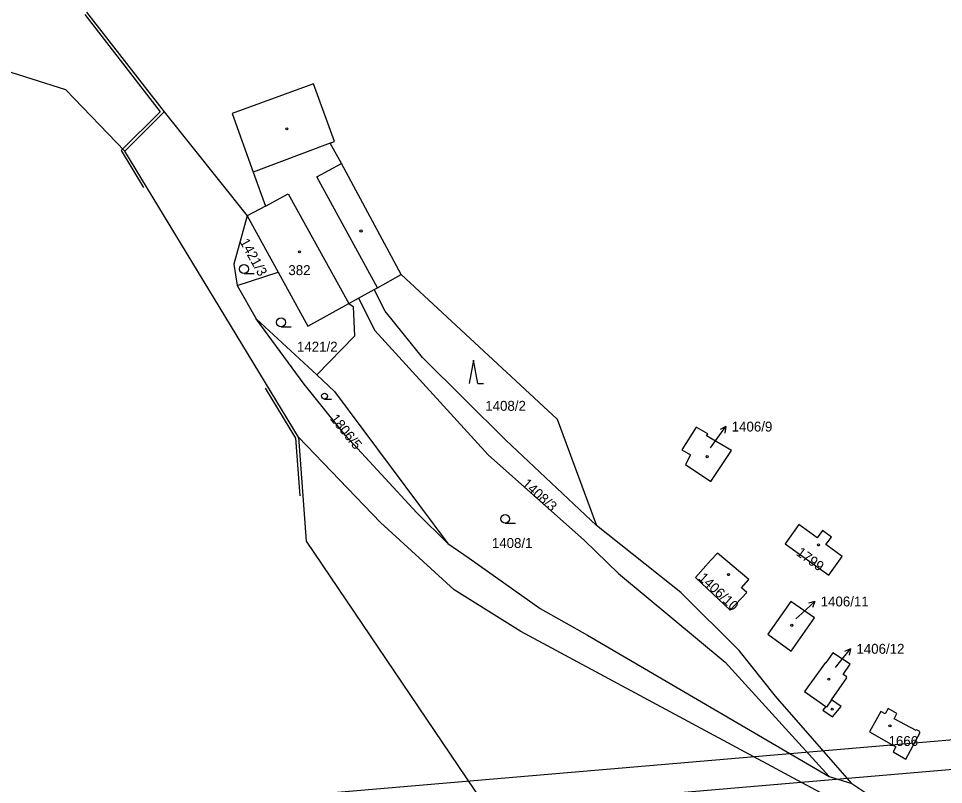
# Model space of a CAD drawing. Extents: x -779330 to -774454, y -1144748 to -1142831.
# Drawn here: x -778476.8 to -778318.4, y -1143557.2 to -1143426 of the extents above; entities that cross this region are included whole.
import ezdxf

# ---------------------------------------------------------------- set-up
doc = ezdxf.new("R2010")
doc.units = 0
for name, color, linetype in [('Hranice parcel', 7, 'Continuous'), ('Parcelní čísla', 7, 'Continuous'), ('Pop  PČ popisy', 7, 'Continuous'), ('Vnitřní kresba', 7, 'Continuous'), ('Vrstva 1', 7, 'Continuous'), ('Značky budov', 7, 'Continuous'), ('Značky kultur', 7, 'Continuous')]:
    doc.layers.add(name, color=color, linetype=linetype)

msp = doc.modelspace()

# ---------------------------------------------------------------- linework, layer by layer
at = {"layer": 'Hranice parcel'}
for p, q in [((-778465.13, -1143424.95), (-778451.86, -1143442.04)), ((-778468.65, -1143438.25), (-778504.96, -1143426.73)), ((-778458.56, -1143448.73), (-778468.65, -1143438.25)), ((-778458.56, -1143448.73), (-778451.86, -1143442.04)), ((-778451.86, -1143442.04), (-778437.65, -1143459.82)), ((-778428.85, -1143497.7), (-778458.56, -1143448.73)), ((-778437.65, -1143459.82), (-778432.35, -1143469.46)), ((-778439.35, -1143471.76), (-778432.35, -1143469.46)), ((-778439.35, -1143471.76), (-778436.1, -1143477.46)), ((-778418.6, -1143473.93), (-778415.92, -1143472.44)), ((-778420.24, -1143474.84), (-778418.6, -1143473.93)), ((-778436.1, -1143477.46), (-778425.71, -1143487.05)), ((-778427.89, -1143488.63), (-778436.1, -1143477.46)), ((-778419.29, -1143480.44), (-778425.71, -1143487.05)), ((-778403.28, -1143515.89), (-778408.6, -1143510.68)), ((-778403.28, -1143515.89), (-778399.61, -1143518.42)), ((-778338.03, -1143555.79), (-778334.13, -1143557.01))]:
    msp.add_line(p, q, dxfattribs=at)
for points in [[(-778411.25, -1143469.85), (-778421.51, -1143450.89), (-778423.42, -1143447.36), (-778422.68, -1143447.08), (-778426.28, -1143437.21), (-778440.22, -1143442.3), (-778436.59, -1143452.33), (-778434.47, -1143458.19), (-778437.65, -1143459.82)], [(-778437.65, -1143459.82), (-778439.93, -1143468.1), (-778439.35, -1143471.76)], [(-778432.35, -1143469.46), (-778427.25, -1143478.73), (-778420.24, -1143474.84)], [(-778415.92, -1143472.44), (-778415.35, -1143472.13), (-778411.25, -1143469.85)], [(-778411.25, -1143469.85), (-778384.6, -1143494.61), (-778377.84, -1143512.85)], [(-778377.84, -1143512.85), (-778393.35, -1143498.23), (-778407.6, -1143484.07), (-778414.02, -1143476.15), (-778415.92, -1143472.44)], [(-778420.24, -1143474.84), (-778419.49, -1143475.35), (-778419.29, -1143480.44)], [(-778418.6, -1143473.93), (-778415.77, -1143479.46), (-778396.37, -1143500.75), (-778379.92, -1143515.38), (-778374.08, -1143521.03), (-778355.81, -1143536.2), (-778338.03, -1143555.79)], [(-778425.71, -1143487.05), (-778422.69, -1143489.91), (-778403.28, -1143515.89)], [(-778408.6, -1143510.68), (-778420.83, -1143497.44), (-778427.89, -1143488.63)], [(-778363.25, -1143499.87), (-778361.75, -1143500.75), (-778362.6, -1143502.4), (-778358.29, -1143505.3), (-778354.71, -1143499.97), (-778358.99, -1143497.46), (-778358.81, -1143497.14), (-778360.79, -1143495.98), (-778363.25, -1143499.87)], [(-778273.31, -1143597.02), (-778277.63, -1143592.38), (-778304.71, -1143577.98), (-778330.53, -1143563.4), (-778390.82, -1143530.99), (-778402.19, -1143523.83), (-778414.83, -1143512.31), (-778428.85, -1143497.7)], [(-778428.85, -1143497.7), (-778427.52, -1143515.51), (-778391.96, -1143568.16), (-778391.52, -1143569.91)], [(-778334.13, -1143557.01), (-778347.2, -1143542.07), (-778353.41, -1143534.24), (-778363.4, -1143524.31), (-778377.84, -1143512.85)], [(-778338.07, -1143521.32), (-778335.78, -1143518.13), (-778338.56, -1143516.07), (-778337.63, -1143514.81), (-778339.14, -1143513.69), (-778340.08, -1143514.96), (-778343.19, -1143512.66), (-778345.56, -1143515.98), (-778338.07, -1143521.32)], [(-778360.92, -1143521.73), (-778354.94, -1143527.3), (-778352.13, -1143524.28), (-778353.02, -1143523.48), (-778351.76, -1143522.08), (-778357.15, -1143517.55), (-778358.26, -1143518.78), (-778360.92, -1143521.73)], [(-778399.61, -1143518.42), (-778387.5, -1143527.04), (-778379.4, -1143531.58), (-778338.03, -1143555.79)], [(-778348.49, -1143531.41), (-778344.5, -1143534.34), (-778340.52, -1143528.66), (-778344.56, -1143525.82), (-778348.49, -1143531.41)], [(-778338.57, -1143536.35), (-778338.67, -1143536.28), (-778342.22, -1143541.27), (-778338.58, -1143543.81), (-778339.08, -1143544.45), (-778337.43, -1143545.61), (-778335.97, -1143543.84), (-778337.61, -1143542.7), (-778334.98, -1143538.91), (-778335.1, -1143538.83), (-778335.02, -1143538.71), (-778335.62, -1143538.31), (-778334.45, -1143536.55), (-778337.4, -1143534.61), (-778338.57, -1143536.35)], [(-778323.15, -1143547.92), (-778326.89, -1143545.9), (-778326.41, -1143545), (-778327.93, -1143544.15), (-778328.43, -1143545.08), (-778329.2, -1143544.66), (-778331.1, -1143548.17), (-778326.58, -1143550.7), (-778327.08, -1143551.6), (-778324.88, -1143552.84), (-778322.44, -1143548.29), (-778322.58, -1143548.22), (-778322.5, -1143548.09), (-778323.07, -1143547.78), (-778323.15, -1143547.92)], [(-778334.13, -1143557.01), (-778329.33, -1143560.21), (-778314.57, -1143568.39), (-778292.12, -1143578.54), (-778273.65, -1143590.2)]]:
    msp.add_lwpolyline(points, dxfattribs=at)
at = {"layer": 'Pop  PČ popisy'}
for p, q in [((-778357.47, -1143498.32), (-778355.71, -1143495.89)), ((-778355.71, -1143495.89), (-778356.7, -1143496.41)), ((-778355.71, -1143495.89), (-778355.89, -1143497)), ((-778358.35, -1143499.52), (-778357.47, -1143498.32)), ((-778342.67, -1143527.88), (-778340.47, -1143525.83)), ((-778340.47, -1143525.83), (-778341.55, -1143526.15)), ((-778340.47, -1143525.83), (-778340.87, -1143526.88)), ((-778343.7, -1143528.83), (-778342.67, -1143527.88)), ((-778336.25, -1143536.26), (-778334.36, -1143533.93)), ((-778334.36, -1143533.93), (-778335.38, -1143534.39)), ((-778334.36, -1143533.93), (-778334.6, -1143535.02)), ((-778336.94, -1143537.11), (-778336.25, -1143536.26))]:
    msp.add_line(p, q, dxfattribs=at)
at = {"layer": 'Vnitřní kresba'}
for p, q in [((-778465.44, -1143425.36), (-778452.52, -1143442)), ((-778459.19, -1143448.66), (-778452.52, -1143442)), ((-778423.42, -1143447.36), (-778436.59, -1143452.33)), ((-778459.19, -1143448.66), (-778455.37, -1143454.96)), ((-778425.7, -1143453.15), (-778421.51, -1143450.89)), ((-778415.35, -1143472.13), (-778425.7, -1143453.15)), ((-778434.47, -1143458.19), (-778430.62, -1143456.06)), ((-778430.62, -1143456.06), (-778420.24, -1143474.84)), ((-778434.53, -1143489.3), (-778429.34, -1143497.86)), ((-778429.34, -1143497.86), (-778428.6, -1143507.77)), ((-778337.61, -1143542.7), (-778338.45, -1143543.9)), ((-778338.45, -1143543.9), (-778338.58, -1143543.81))]:
    msp.add_line(p, q, dxfattribs=at)
at = {"layer": 'Vrstva 1'}
for points in [[(-777571, -1143485.76), (-778617.18, -1143575.21), (-778591.88, -1143871.12), (-777545.7, -1143781.67)], [(-777551.11, -1143777.12), (-778587.32, -1143865.71), (-778611.77, -1143579.77), (-777575.56, -1143491.17)]]:
    msp.add_lwpolyline(points, close=True, dxfattribs=at)
at = {"layer": 'Značky budov'}
for centre in [(-778430.86, -1143444.93), (-778418.15, -1143462.42), (-778428.68, -1143465.98), (-778358.89, -1143501.05), (-778339.85, -1143516.16), (-778355.26, -1143521.24), (-778344.42, -1143529.92), (-778338.09, -1143539.14), (-778337.5, -1143544.27), (-778327.61, -1143547.12)]:
    msp.add_circle(centre, 0.175, dxfattribs=at)
at = {"layer": 'Značky kultur'}
for p, q in [((-778438.17, -1143469.68), (-778436.42, -1143469.68)), ((-778431.84, -1143478.81), (-778430.09, -1143478.81)), ((-778398.91, -1143484.51), (-778399.66, -1143488.51)), ((-778398.16, -1143488.51), (-778398.91, -1143484.51)), ((-778398.16, -1143488.51), (-778397.16, -1143488.51)), ((-778424.4, -1143491.18), (-778423.22, -1143491.18)), ((-778393.48, -1143512.44), (-778391.73, -1143512.44))]:
    msp.add_line(p, q, dxfattribs=at)
for centre, radius in [((-778438.17, -1143468.93), 0.75), ((-778431.84, -1143478.06), 0.75), ((-778424.4, -1143490.68), 0.502), ((-778393.48, -1143511.69), 0.75)]:
    msp.add_circle(centre, radius, dxfattribs=at)

# ---------------------------------------------------------------- texts
at = {"layer": 'Parcelní čísla'}
for s, rotation, p in [('1421/3', 299, (-778438.96, -1143464.26)), ('1806/5', 309, (-778423.54, -1143494.58)), ('1408/3', 318, (-778390.72, -1143505.88)), ('1799', 324, (-778343.79, -1143517.79)), ('1406/10', 317, (-778360.52, -1143521.96))]:
    msp.add_text(s, height=1.7, rotation=rotation, dxfattribs=at).set_placement(p)
for s, p in [('382', (-778430.58, -1143469.97)), ('1421/2', (-778429.11, -1143483.07)), ('1408/2', (-778396.88, -1143493.2)), ('1406/9', (-778354.7, -1143496.75)), ('1408/1', (-778395.75, -1143516.68)), ('1406/11', (-778339.47, -1143526.69)), ('1406/12', (-778333.35, -1143534.79)), ('1666', (-778327.85, -1143550.58))]:
    msp.add_text(s, height=1.7, dxfattribs=at).set_placement(p)

doc.saveas('drawing.dxf')
